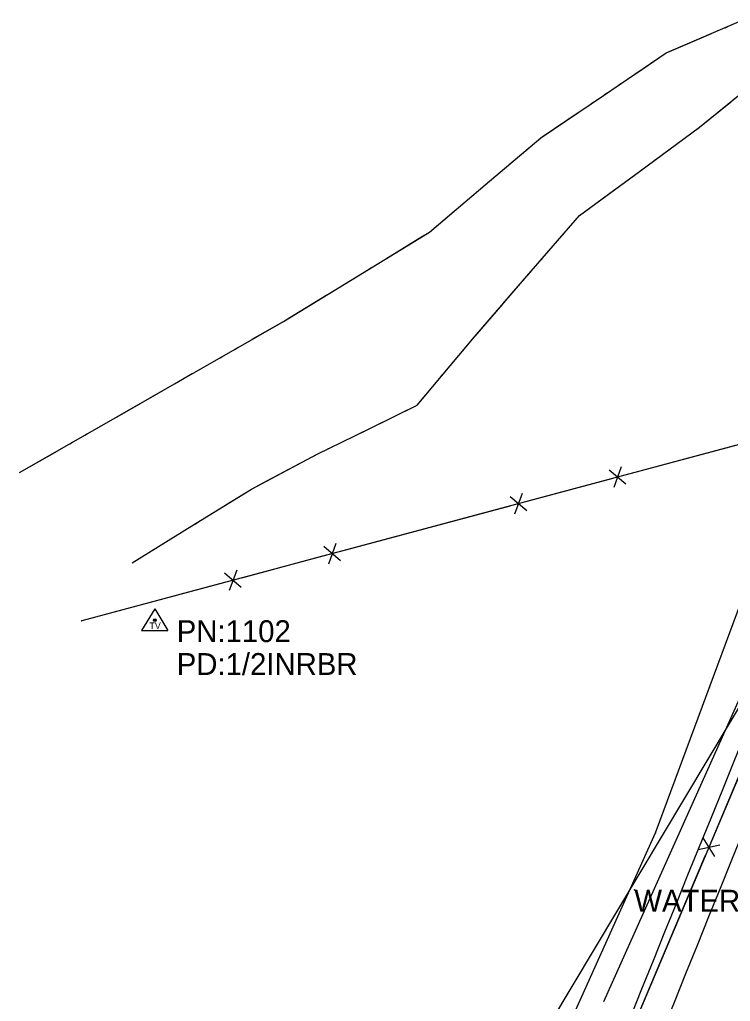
# Model space of a CAD drawing. Extents: x 1282810 to 1284464, y 402460 to 405899.
# Drawn here: x 1283129.5 to 1283291.6, y 403680.6 to 403904.7 of the extents above; entities that cross this region are included whole.
import ezdxf

# ---------------------------------------------------------------- set-up
doc = ezdxf.new("R2010")
doc.units = 0
for name, color, linetype in [('MOT_Proposed Road_Stage 2', 7, 'Continuous'), ('MOT_Shld_Stage 2', 7, 'Continuous'), ('MOT_Stage 2_Retaining Wall', 7, 'Continuous'), ('S_FENCE', 7, 'Continuous'), ('S_MSC_PT_SYM', 7, 'Continuous'), ('S_SECONDARY_CTL', 7, 'Continuous'), ('S_SECONDARY_CTL_ANNOT', 7, 'Continuous'), ('S_STREAM', 7, 'Continuous'), ('S_SURVEY_TEXT_ANNOT', 7, 'Continuous'), ('S_UNDERGROUND_CABLE', 7, 'Continuous'), ('S_UTL_PT_SYM', 7, 'Continuous'), ('S_WATER_UTILITIES', 7, 'Continuous')]:
    doc.layers.add(name, color=color, linetype=linetype)

msp = doc.modelspace()

# ---------------------------------------------------------------- linework, layer by layer
at = {"layer": 'MOT_Proposed Road_Stage 2'}
for radius in [11483.16, 11461.16]:
    msp.add_arc((1293930.9, 399391.32), radius, 157.333333, 159.572534, dxfattribs=at)
at = {"layer": 'MOT_Shld_Stage 2'}
msp.add_line((1283262.75, 403680.57), (1283303.81, 403772.18), dxfattribs=at)
msp.add_arc((1293930.9, 399391.32), 11491.16, 157.333333, 159.572534, dxfattribs=at)
msp.add_arc((1293930.9, 399391.32), 11491.16, 157.333333, 159.572534, dxfattribs=at)
at = {"layer": 'MOT_Stage 2_Retaining Wall'}
for radius in [11458.66, 11457.16]:
    msp.add_arc((1293930.9, 399391.32), radius, 157.333333, 159.562079, dxfattribs=at)
at = {"layer": 'S_FENCE'}
for p, q in [((1283329.66, 403817.36), (1283143.67, 403767.43)), ((1283261.12, 403654.99), (1283329.66, 403817.36)), ((1283267.83, 403798.64), (1283264, 403801.85)), ((1283266.77, 403802.6), (1283265.06, 403797.9)), ((1283245.2, 403792.56), (1283241.37, 403795.78)), ((1283244.14, 403796.52), (1283242.43, 403791.82)), ((1283202.71, 403781.16), (1283198.88, 403784.37)), ((1283201.64, 403785.11), (1283199.94, 403780.41)), ((1283180.07, 403775.08), (1283176.24, 403778.29)), ((1283179.01, 403779.04), (1283177.3, 403774.34)), ((1283288.11, 403713.66), (1283285.45, 403717.89)), ((1283284.33, 403715.25), (1283289.22, 403716.3))]:
    msp.add_line(p, q, dxfattribs=at)
for points in [[(1283306.48, 403811.13), (1283267.85, 403800.76)], [(1283264.53, 403799.87), (1283245.22, 403794.69)], [(1283241.35, 403793.65), (1283202.72, 403783.28)], [(1283199.41, 403782.39), (1283180.09, 403777.21)], [(1283176.23, 403776.17), (1283143.67, 403767.43)], [(1283287.34, 403717.1), (1283295.11, 403735.52)], [(1283270.45, 403677.1), (1283286, 403713.93)]]:
    msp.add_lwpolyline(points, dxfattribs=at)
at = {"layer": 'S_MSC_PT_SYM'}
for points in [[(1283143.67, 403767.43), (1283143.67, 403767.48), (1283143.67, 403767.43), (1283143.62, 403767.43), (1283143.67, 403767.43), (1283143.67, 403767.38), (1283143.67, 403767.43), (1283143.72, 403767.43)], [(1283269.74, 403706.04), (1283269.74, 403706.09), (1283269.74, 403706.04), (1283269.69, 403706.04), (1283269.74, 403706.04), (1283269.74, 403705.99), (1283269.74, 403706.04), (1283269.79, 403706.04)]]:
    msp.add_lwpolyline(points, dxfattribs=at)
at = {"layer": 'S_SECONDARY_CTL'}
for p, q in [((1283160.34, 403770.18), (1283157.33, 403765.23)), ((1283160.34, 403770.18), (1283163.29, 403765.23)), ((1283157.33, 403765.23), (1283163.29, 403765.23))]:
    msp.add_line(p, q, dxfattribs=at)
for radius in [0.311, 0.183, 0.103]:
    msp.add_circle((1283160.34, 403767.57), radius, dxfattribs=at)
at = {"layer": 'S_STREAM'}
for points in [[(1283129.5, 403801.27), (1283147.15, 403811.4), (1283164.8, 403821.53), (1283177.23, 403828.65), (1283189.66, 403835.76), (1283206.34, 403845.97), (1283223.02, 403856.19), (1283235.69, 403866.94), (1283248.37, 403877.69), (1283262.7, 403887.39), (1283277.03, 403897.09), (1283294.74, 403904.68)], [(1283290.43, 403902.83), (1283291.08, 403903.11)], [(1283278.29, 403897.63), (1283287.36, 403901.52)], [(1283155.14, 403780.67), (1283168.76, 403789.1), (1283182.38, 403797.52), (1283197.41, 403805.48), (1283208.78, 403811.07), (1283220.16, 403816.66), (1283233.26, 403832.25), (1283245.23, 403846.1), (1283257.2, 403859.95), (1283270.89, 403870.02), (1283284.59, 403880.1), (1283303.96, 403895.89), (1283313.81, 403885.53), (1283332.16, 403884.74), (1283350.5, 403883.96), (1283361.12, 403861.52), (1283371.83, 403855.95), (1283372.66, 403855.71)], [(1283269.98, 403892.32), (1283277.03, 403897.09), (1283278.28, 403897.63)], [(1283266.21, 403889.77), (1283266.81, 403890.17)], [(1283262.94, 403887.56), (1283263.54, 403887.96)], [(1283259.67, 403885.34), (1283260.26, 403885.74)], [(1283284.11, 403879.74), (1283284.59, 403880.1), (1283291.64, 403885.85)], [(1283248.74, 403877.94), (1283256.91, 403883.47)], [(1283241.17, 403871.58), (1283248.37, 403877.69), (1283248.73, 403877.93)], [(1283280.51, 403877.1), (1283281.08, 403877.51)], [(1283277.39, 403874.8), (1283277.95, 403875.22)], [(1283274.26, 403872.5), (1283274.83, 403872.92)], [(1283237.7, 403868.64), (1283238.25, 403869.1)], [(1283263.82, 403864.82), (1283270.89, 403870.02), (1283271.63, 403870.56)], [(1283234.69, 403866.09), (1283235.24, 403866.55)], [(1283256.22, 403858.82), (1283257.2, 403859.95), (1283263.81, 403864.81)], [(1283231.68, 403863.53), (1283232.22, 403864)], [(1283221.44, 403855.22), (1283223.02, 403856.19), (1283229.13, 403861.38)], [(1283253.31, 403855.45), (1283253.77, 403855.98)], [(1283213.01, 403850.06), (1283221.43, 403855.22)], [(1283250.77, 403852.51), (1283251.23, 403853.04)], [(1283248.23, 403849.58), (1283248.69, 403850.11)], [(1283209.13, 403847.69), (1283209.74, 403848.06)], [(1283239.75, 403839.77), (1283245.23, 403846.1), (1283246.09, 403847.1)], [(1283205.76, 403845.62), (1283206.34, 403845.97), (1283206.37, 403846)], [(1283202.4, 403843.56), (1283203.01, 403843.93)], [(1283191.13, 403836.66), (1283199.55, 403841.82)], [(1283233.41, 403832.43), (1283239.75, 403839.76)], [(1283182.58, 403831.71), (1283189.66, 403835.76), (1283191.12, 403836.66)], [(1283178.64, 403829.45), (1283179.26, 403829.81)], [(1283230.53, 403829.01), (1283230.99, 403829.55)], [(1283175.21, 403827.49), (1283175.83, 403827.84)], [(1283228.04, 403826.04), (1283228.49, 403826.58)], [(1283171.78, 403825.53), (1283172.4, 403825.88)], [(1283160.32, 403818.96), (1283164.8, 403821.53), (1283168.89, 403823.87)], [(1283225.54, 403823.07), (1283225.99, 403823.61)], [(1283216.03, 403814.64), (1283220.16, 403816.66), (1283223.44, 403820.57)], [(1283151.75, 403814.04), (1283160.31, 403818.96)], [(1283207.32, 403810.36), (1283208.78, 403811.07), (1283216.02, 403814.63)], [(1283147.8, 403811.78), (1283148.42, 403812.13)], [(1283144.38, 403809.81), (1283145, 403810.17)], [(1283203.32, 403808.39), (1283203.95, 403808.7)], [(1283129.5, 403801.27), (1283138.06, 403806.19)], [(1283140.95, 403807.85), (1283141.57, 403808.2)], [(1283199.84, 403806.68), (1283200.47, 403806.99)], [(1283196.37, 403804.94), (1283196.99, 403805.26)], [(1283184.91, 403798.86), (1283193.48, 403803.4)], [(1283176.56, 403793.92), (1283182.38, 403797.52), (1283184.9, 403798.86)], [(1283172.77, 403791.58), (1283173.37, 403791.95)], [(1283169.47, 403789.54), (1283170.07, 403789.9)], [(1283166.17, 403787.5), (1283166.77, 403787.86)], [(1283155.14, 403780.67), (1283163.39, 403785.77)]]:
    msp.add_lwpolyline(points, dxfattribs=at)
at = {"layer": 'S_UNDERGROUND_CABLE'}
msp.add_line((1283240.13, 403658.24), (1283340.02, 403825.33), dxfattribs=at)
at = {"layer": 'S_UTL_PT_SYM'}
msp.add_lwpolyline([(1283274.53, 403719.02), (1283274.53, 403719.07), (1283274.53, 403719.02), (1283274.48, 403719.02), (1283274.53, 403719.02), (1283274.53, 403718.97), (1283274.53, 403719.02), (1283274.58, 403719.02)], dxfattribs=at)
at = {"layer": 'S_WATER_UTILITIES'}
for p, q in [((1283274.53, 403719.02), (1283298.04, 403782.43)), ((1283252.04, 403668.99), (1283274.53, 403719.02))]:
    msp.add_line(p, q, dxfattribs=at)

# ---------------------------------------------------------------- texts
at = {"layer": 'S_SECONDARY_CTL'}
msp.add_text('TV', height=1.5, rotation=360, dxfattribs=at).set_placement((1283159.13, 403765.56))
at = {"layer": 'S_SECONDARY_CTL_ANNOT'}
for s, p in [('PN:1102', (1283165.34, 403762.57)), ('PD:1/2INRBR', (1283165.34, 403755.07))]:
    msp.add_text(s, height=5, dxfattribs=at).set_placement(p)
at = {"layer": 'S_SURVEY_TEXT_ANNOT'}
msp.add_text('WATERLINE LEAK', height=5, dxfattribs=at).set_placement((1283269.74, 403701.04))

doc.saveas('drawing.dxf')
